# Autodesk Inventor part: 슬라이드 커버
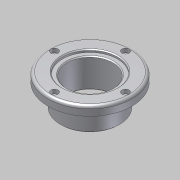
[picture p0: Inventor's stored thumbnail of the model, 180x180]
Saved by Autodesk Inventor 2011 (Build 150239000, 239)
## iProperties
Created: 2013-06
Part Number: 슬라이드 커버
Document SubType Name: Modeling
Designer: SeoGD™[esajin.kr]
Density: 1 g/cm^3
Mass: 75.9731 g
Surface Area: 227.998 cm^2
Volume: 75.9731 cm^3
Author: SeoGD™[esajin.kr]
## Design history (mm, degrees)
sketch "스케치1"
  geometry: C1 r 46 at (0, -39.25) reference; C2 r 32.5 at (0, -39.25) reference; 1 further point
  node "참조1"
  node "참조2"
extrude "돌출1" new body sketch "스케치1" distance "d0" = 10; taper "d1" = 0 deg
extrude "돌출2" join sketch "스케치1" distance "d2" = 25; taper "d3" = 0 deg
hole "구멍1" diameter "d6" = 50; stored, may be unused: countersink angle "d10" = 90 deg, drill point angle "d12" = 118 deg; dims "d4" = 10, "d5" = 10, "d7" = 6, "d8" = 4, "d9" = 2, "d11" = 8
sketch "스케치2"
  geometry: C1 r 46 at (0, 0) reference; C2 r 1.621 at (0, 39) reference; C3 r 1.621 at (39, 0) reference; C4 r 1.621 at (0, -39) reference; C5 r 1.621 at (-39, 0) reference; C6 r 33.5 at (0, 0) reference; 1 further point
hole "구멍2" sketch "스케치2" at (0, 39) diameter "d13" = 4.5; stored, may be unused: countersink angle "d17" = 90 deg, drill point angle "d19" = 118 deg; dims "d14" = 6, "d15" = 8, "d16" = 4.4, "d18" = 8
fillet "모깎기1" dims "d23" = 3
chamfer "모따기1" distance "d24" = 1; stored, may be unused: second distance "d25" = 2, angle "d26" = 45 deg
sketch "스케치3"
  geometry: C1 r 25 at (39, 0) reference; C2 r 30 at (39, 0); 1 further point
  constraints: 1 centre point, 1 coincident
  dimensions: "d27" = 60 diameter of C2
extrude "돌출3" cut sketch "스케치3" distance "d28" = 3; taper "d29" = 0 deg
chamfer "모따기2" distance "d30" = 1; stored, may be unused: second distance "d31" = 2, angle "d32" = 45 deg
node "솔리드1"
pattern_circular "원형 패턴1" dims angle "d21" = 360 deg
node "참조3"
